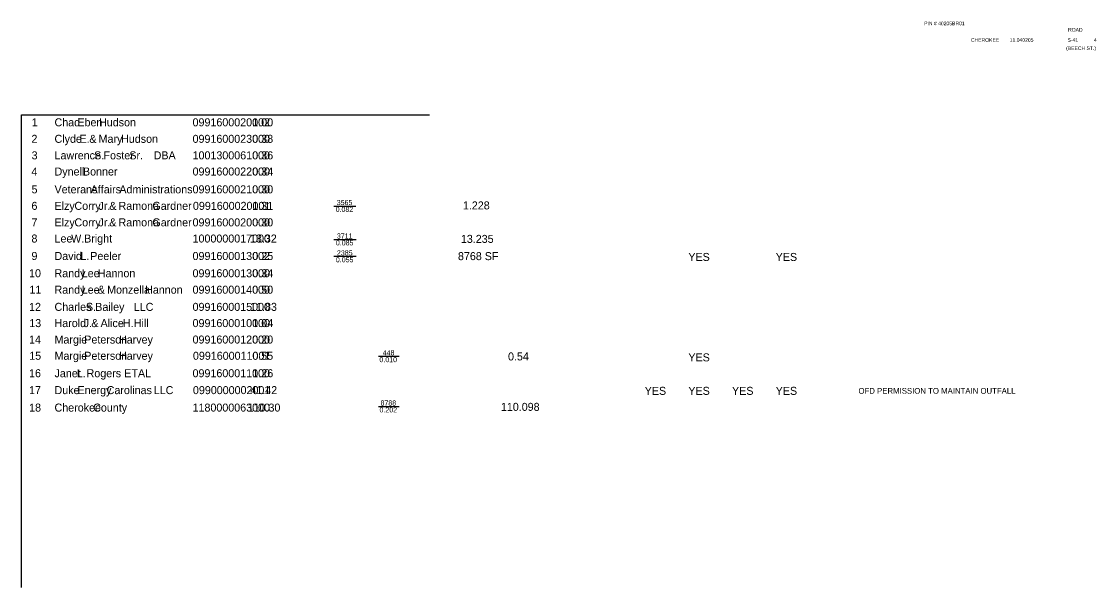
# Model space of a CAD drawing. Extents: x 160093 to 164626, y 177093 to 182727.
# Drawn here: x 163090 to 164568, y 179650 to 180427 of the extents above; entities that cross this region are included whole.
import ezdxf

# ---------------------------------------------------------------- set-up
doc = ezdxf.new("R2010")
doc.units = 0
doc.layers.add('Default', color=7, linetype='Continuous')
doc.layers.add('Level 40', color=7, linetype='Continuous')

msp = doc.modelspace()

# ---------------------------------------------------------------- linework, layer by layer
at = {"layer": 'Default'}
for p, q in [((163090.4, 180299), (163090.4, 180299)), ((163090.4, 179649.7), (163090.4, 180299)), ((163090.4, 180299), (163651, 180299)), ((163519.4, 180173.8), (163549.8, 180173.8)), ((163519.8, 180127.8), (163550.1, 180127.8)), ((163519.8, 180104.8), (163550.1, 180104.8)), ((163581, 179967.5), (163609.3, 179967.5)), ((163581, 179898.5), (163609.3, 179898.5))]:
    msp.add_line(p, q, dxfattribs=at)

# ---------------------------------------------------------------- texts
for s, height, p in [('ROAD', 5, (164528.6, 180413.5)), ('11.040205', 5, (164448.4, 180399.5)), (' S-41', 5, (164525.9, 180399.5)), ('(BEECH ST.)', 5, (164525.9, 180388.3)), ('1', 11, (163104.5, 180283.4)), ('Chad', 11, (163135.8, 180283.4)), (' Eben', 11, (163163.1, 180283.4)), (' Hudson', 11, (163192.9, 180283.4)), ('0991600020002', 11, (163325.5, 180283.4)), ('1.00', 11, (163407.6, 180283.4)), ('2', 11, (163104.1, 180260.7)), ('Clyde', 11, (163135.8, 180260.7)), (' E.', 11, (163166.1, 180260.7)), (' &', 11, (163179.6, 180260.7)), (' Mary', 11, (163192.3, 180260.7)), (' Hudson', 11, (163223.2, 180260.7)), ('0991600023000', 11, (163325.5, 180260.7)), ('0.38', 11, (163407.6, 180260.7)), ('3', 11, (163104.3, 180238)), ('Lawrence', 11, (163135.8, 180238)), (' S.', 11, (163186.2, 180238)), (' Foster', 11, (163199, 180238)), (' Sr.', 11, (163234.5, 180238)), ('     DBA', 11, (163251.6, 180238)), ('1001300061000', 11, (163325.5, 180238)), ('0.36', 11, (163407.6, 180238)), ('4', 11, (163104.1, 180215.8)), ('Dynell', 11, (163135.8, 180215.8)), (' Bonner', 11, (163170.8, 180215.8)), ('0991600022000', 11, (163325.5, 180215.8)), ('0.34', 11, (163407.7, 180215.8)), ('5', 11, (163104.2, 180191.3)), ('Veterans', 11, (163135.8, 180191.3)), (' Affairs', 11, (163181.4, 180191.3)), (' Administrations', 11, (163220.8, 180191.3)), ('0991600021000', 11, (163325.5, 180191.3)), ('0.30', 11, (163407.6, 180191.3)), ('6', 11, (163104.1, 180168.6)), ('Elzy', 11, (163135.8, 180168.6)), (' Corry', 11, (163159.1, 180168.6)), (' Jr.', 11, (163192.1, 180168.6)), (' &', 11, (163207, 180168.6)), (' Ramona', 11, (163219.7, 180168.6)), (' Gardner', 11, (163266.2, 180168.6)), ('0991600020001', 11, (163326, 180168.6)), ('1.31', 11, (163407.6, 180168.6)), ('3565', 7, (163523.6, 180175.2)), ('1.228', 11, (163697, 180169.2)), ('0.082', 7, (163522.1, 180165.8)), ('7', 11, (163104.1, 180145.9)), ('Elzy', 11, (163135.8, 180145.9)), (' Corry', 11, (163159.1, 180145.9)), (' Jr.', 11, (163192.1, 180145.9)), (' &', 11, (163207, 180145.9)), (' Ramona', 11, (163219.7, 180145.9)), (' Gardner', 11, (163266.2, 180145.9)), ('0991600020000', 11, (163325.5, 180145.9)), ('0.30', 11, (163407.6, 180145.9)), (' Bright', 11, (163172.4, 180123.7)), ('3711', 7, (163523.8, 180129.2)), ('8', 11, (163104.1, 180123.7)), ('Lee', 11, (163135.8, 180123.7)), (' W.', 11, (163154.6, 180123.7)), ('1000000017000', 11, (163325.5, 180123.7)), ('13.32', 11, (163404.4, 180123.7)), ('0.085', 7, (163522.4, 180119.8)), ('13.235', 11, (163694.2, 180123.2)), ('9', 11, (163104.1, 180099.7)), ('David', 11, (163135.8, 180099.7)), (' L.', 11, (163167.4, 180099.7)), (' Peeler', 11, (163180.8, 180099.7)), ('0991600013002', 11, (163325.5, 180099.7)), ('0.25', 11, (163407.7, 180099.7)), ('2385', 7, (163523.9, 180106)), ('8768 SF', 11, (163690.2, 180099.5)), ('YES', 11, (164006.8, 180098.4)), ('YES', 11, (164126.8, 180098.4)), ('0.055', 7, (163522.4, 180096.6)), ('10', 11, (163100.8, 180076)), ('Randy', 11, (163135.8, 180076)), (' Lee', 11, (163169.1, 180076)), (' Hannon', 11, (163191.2, 180076)), ('0991600013000', 11, (163325.5, 180076)), ('0.34', 11, (163407.7, 180076)), ('11', 11, (163101.3, 180053.4)), ('Randy', 11, (163135.8, 180053.4)), (' Lee', 11, (163169.1, 180053.4)), (' &', 11, (163191.2, 180053.4)), (' Monzella', 11, (163204, 180053.4)), (' Hannon', 11, (163256.2, 180053.4)), ('0991600014000', 11, (163325.5, 180053.4)), ('0.50', 11, (163407.6, 180053.4)), ('12', 11, (163100.8, 180029.8)), ('Charles', 11, (163135.8, 180029.8)), (' S.', 11, (163174.9, 180029.8)), (' Bailey', 11, (163187.7, 180029.8)), ('     LLC', 11, (163224.3, 180029.8)), ('0991600015000', 11, (163325.5, 180029.8)), ('11.83', 11, (163404.6, 180029.8)), ('13', 11, (163101.1, 180007.5)), ('Harold', 11, (163135.8, 180007.5)), (' J.', 11, (163171.7, 180007.5)), (' &', 11, (163182.3, 180007.5)), (' Alice', 11, (163195, 180007.5)), (' H.', 11, (163225.7, 180007.5)), (' Hill', 11, (163240.6, 180007.5)), ('0991600010000', 11, (163325.5, 180007.5)), ('1.04', 11, (163407.7, 180007.5)), ('14', 11, (163100.8, 179984.9)), ('Margie', 11, (163135.8, 179984.9)), (' Peterson', 11, (163172.6, 179984.9)), (' Harvey', 11, (163220.3, 179984.9)), ('0991600012000', 11, (163325.5, 179984.9)), ('0.20', 11, (163407.6, 179984.9)), ('15', 11, (163101, 179962.6)), ('Margie', 11, (163135.8, 179962.6)), (' Peterson', 11, (163172.6, 179962.6)), (' Harvey', 11, (163220.3, 179962.6)), ('0991600011001', 11, (163326, 179962.6)), ('0.55', 11, (163407.6, 179962.6)), ('448', 7, (163586.8, 179968.7)), ('0.54', 11, (163759, 179961.7)), ('0.010', 7, (163582.3, 179959.3)), ('YES', 11, (164006.8, 179960.4)), ('16', 11, (163100.8, 179938.6)), ('Janet', 11, (163135.8, 179938.6)), (' L.', 11, (163162.3, 179938.6)), (' Rogers', 11, (163175.8, 179938.6)), ('    ETAL', 11, (163215.3, 179938.6)), ('0991600011000', 11, (163325.5, 179938.6)), ('1.26', 11, (163407.7, 179938.6)), ('17', 11, (163100.8, 179915.4)), ('Duke', 11, (163135.8, 179915.4)), (' Energy', 11, (163163.3, 179915.4)), (' Carolinas', 11, (163203.4, 179915.4)), ('    LLC', 11, (163255.8, 179915.4)), ('0990000002001', 11, (163326, 179915.4)), ('41.42', 11, (163404.9, 179915.4)), ('YES', 11, (163946.8, 179914.4)), ('YES', 11, (164006.8, 179914.4)), ('YES', 11, (164066.8, 179914.4)), ('YES', 11, (164126.8, 179914.4)), ('OFD PERMISSION TO MAINTAIN OUTFALL', 8, (164240.6, 179915.9)), ('18', 11, (163100.9, 179891.4)), ('Cherokee', 11, (163135.8, 179891.4)), (' County', 11, (163184.8, 179891.4)), ('1180000063000', 11, (163325.5, 179891.4)), ('110.30', 11, (163401.2, 179891.4)), ('8788', 7, (163583.8, 179899.7)), ('110.098', 11, (163749.2, 179892.4)), ('0.202', 7, (163582.4, 179890.3))]:
    msp.add_text(s, height=height, dxfattribs=at).set_placement(p)
at = {"layer": 'Level 40'}
for s, p in [('PIN # 40205BR01', (164330.8, 180422.3)), ('CHEROKEE', (164395.1, 180399.5)), ('4', (164564.1, 180399.5))]:
    msp.add_text(s, height=5, dxfattribs=at).set_placement(p)

doc.saveas('drawing.dxf')
